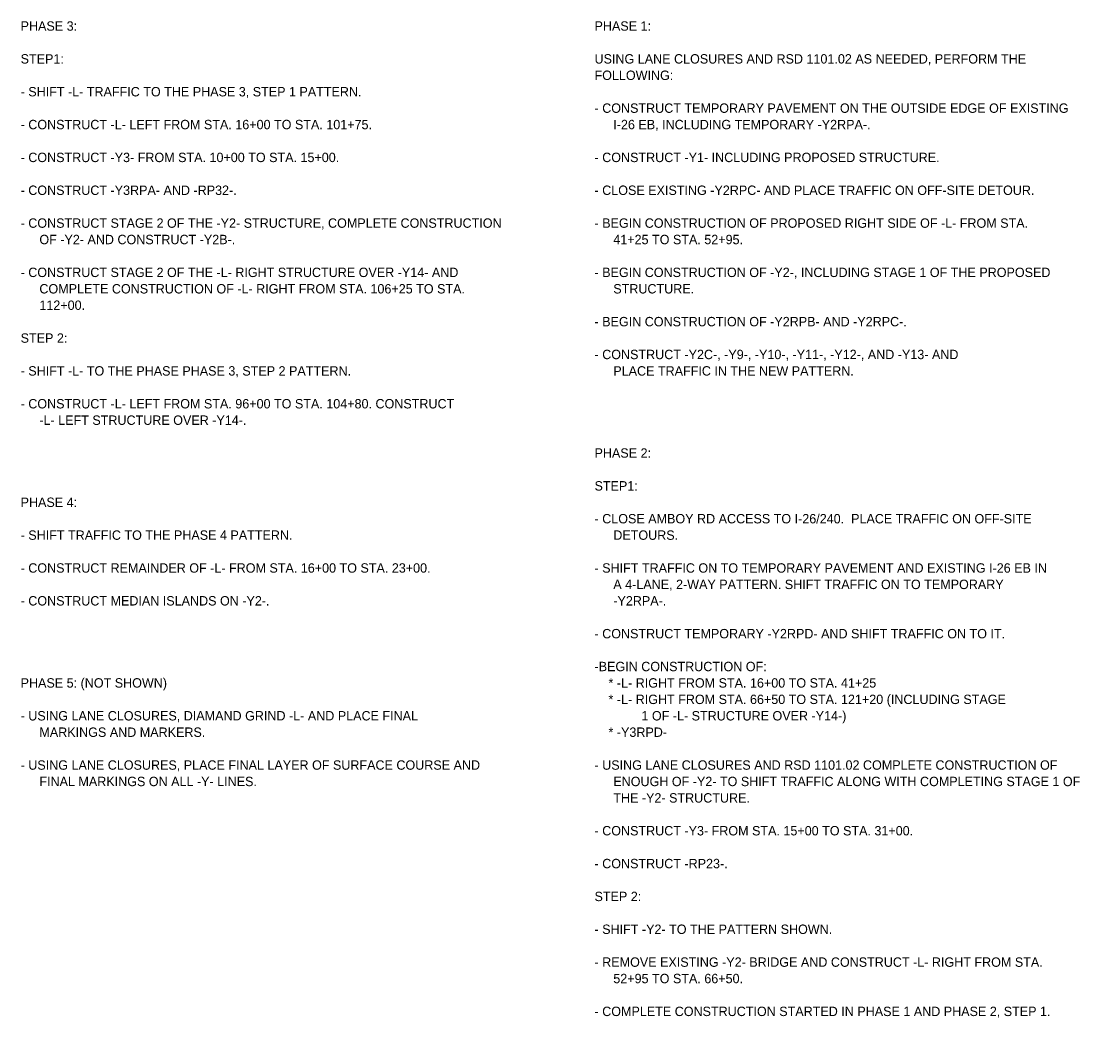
# Model space of a CAD drawing. Extents: x 2483905 to 2494512, y 366160 to 372330.
# Drawn here: x 2485516 to 2486306, y 370427 to 371170 of the extents above; entities that cross this region are included whole.
import ezdxf

# ---------------------------------------------------------------- set-up
doc = ezdxf.new("R2010")
doc.units = 0
doc.layers.add('Scratch_Level_6', color=7, linetype='Continuous')

msp = doc.modelspace()

# ---------------------------------------------------------------- texts
at = {"layer": 'Scratch_Level_6'}
for s, p in [('PHASE 3:', (2485515.8, 371162.6)), ('PHASE 1:', (2485943.99, 371162.6)), ('STEP1:', (2485515.8, 371138.1)), ('USING LANE CLOSURES AND RSD 1101.02 AS NEEDED, PERFORM THE ', (2485943.99, 371138.1)), ('FOLLOWING:', (2485943.99, 371125.86)), ('- SHIFT -L- TRAFFIC TO THE PHASE 3, STEP 1 PATTERN.', (2485515.8, 371113.61)), ('- CONSTRUCT TEMPORARY PAVEMENT ON THE OUTSIDE EDGE OF EXISTING  ', (2485943.99, 371101.36)), ('- CONSTRUCT -L- LEFT FROM STA. 16+00 TO STA. 101+75.', (2485515.8, 371089.12)), ('I-26 EB, INCLUDING TEMPORARY -Y2RPA-.', (2485957.99, 371089.12)), ('- CONSTRUCT -Y3- FROM STA. 10+00 TO STA. 15+00.', (2485515.8, 371064.62)), ('- CONSTRUCT -Y1- INCLUDING PROPOSED STRUCTURE.', (2485943.99, 371064.62)), ('- CONSTRUCT -Y3RPA- AND -RP32-.', (2485515.8, 371040.13)), ('- CLOSE EXISTING -Y2RPC- AND PLACE TRAFFIC ON OFF-SITE DETOUR.', (2485943.99, 371040.13)), ('- CONSTRUCT STAGE 2 OF THE -Y2- STRUCTURE, COMPLETE CONSTRUCTION ', (2485515.8, 371015.64)), ('- BEGIN CONSTRUCTION OF PROPOSED RIGHT SIDE OF -L- FROM STA. ', (2485943.99, 371015.64)), ('OF -Y2- AND CONSTRUCT -Y2B-.', (2485529.8, 371003.39)), ('41+25 TO STA. 52+95.', (2485957.99, 371003.39)), ('- CONSTRUCT STAGE 2 OF THE -L- RIGHT STRUCTURE OVER -Y14- AND ', (2485515.8, 370978.9)), ('- BEGIN CONSTRUCTION OF -Y2-, INCLUDING STAGE 1 OF THE PROPOSED ', (2485943.99, 370978.9)), ('COMPLETE CONSTRUCTION OF -L- RIGHT FROM STA. 106+25 TO STA. ', (2485529.8, 370966.65)), ('STRUCTURE.', (2485957.99, 370966.65)), ('112+00.', (2485529.8, 370954.41)), ('- BEGIN CONSTRUCTION OF -Y2RPB- AND -Y2RPC-.', (2485943.99, 370942.16)), ('STEP 2:', (2485515.8, 370929.91)), ('- CONSTRUCT -Y2C-, -Y9-, -Y10-, -Y11-, -Y12-, AND -Y13- AND ', (2485943.99, 370917.67)), ('- SHIFT -L- TO THE PHASE PHASE 3, STEP 2 PATTERN.', (2485515.8, 370905.42)), ('PLACE TRAFFIC IN THE NEW PATTERN.', (2485957.99, 370905.42)), ('- CONSTRUCT -L- LEFT FROM STA. 96+00 TO STA. 104+80. CONSTRUCT ', (2485515.8, 370880.93)), ('-L- LEFT STRUCTURE OVER -Y14-.', (2485529.8, 370868.68)), ('PHASE 2:', (2485943.99, 370844.19)), ('STEP1:', (2485943.99, 370819.69)), ('PHASE 4:', (2485515.8, 370807.45)), ('- CLOSE AMBOY RD ACCESS TO I-26/240.  PLACE TRAFFIC ON OFF-SITE ', (2485943.99, 370795.2)), ('- SHIFT TRAFFIC TO THE PHASE 4 PATTERN.', (2485515.8, 370782.96)), ('DETOURS.', (2485957.99, 370782.96)), ('- CONSTRUCT REMAINDER OF -L- FROM STA. 16+00 TO STA. 23+00.', (2485515.8, 370758.46)), ('- SHIFT TRAFFIC ON TO TEMPORARY PAVEMENT AND EXISTING I-26 EB IN ', (2485943.99, 370758.46)), ('A 4-LANE, 2-WAY PATTERN. SHIFT TRAFFIC ON TO TEMPORARY          ', (2485957.99, 370746.22)), ('- CONSTRUCT MEDIAN ISLANDS ON -Y2-.', (2485515.8, 370733.97)), ('-Y2RPA-.', (2485957.99, 370733.97)), ('- CONSTRUCT TEMPORARY -Y2RPD- AND SHIFT TRAFFIC ON TO IT.', (2485943.99, 370709.48)), ('-BEGIN CONSTRUCTION OF:', (2485943.99, 370684.98)), ('PHASE 5: (NOT SHOWN)', (2485515.8, 370672.74)), ('    * -L- RIGHT FROM STA. 16+00 TO STA. 41+25', (2485943.99, 370672.74)), ('    * -L- RIGHT FROM STA. 66+50 TO STA. 121+20 (INCLUDING STAGE ', (2485943.99, 370660.49)), ('- USING LANE CLOSURES, DIAMAND GRIND -L- AND PLACE FINAL ', (2485515.8, 370648.24)), ('1 OF -L- STRUCTURE OVER -Y14-)', (2485978.99, 370648.24)), ('MARKINGS AND MARKERS.', (2485529.8, 370636)), ('    * -Y3RPD-', (2485943.99, 370636)), ('- USING LANE CLOSURES, PLACE FINAL LAYER OF SURFACE COURSE AND ', (2485515.8, 370611.5)), ('- USING LANE CLOSURES AND RSD 1101.02 COMPLETE CONSTRUCTION OF ', (2485943.99, 370611.5)), ('FINAL MARKINGS ON ALL -Y- LINES.', (2485529.8, 370599.26)), ('ENOUGH OF -Y2- TO SHIFT TRAFFIC ALONG WITH COMPLETING STAGE 1 OF ', (2485957.99, 370599.26)), ('THE -Y2- STRUCTURE.', (2485957.99, 370587.01)), ('- CONSTRUCT -Y3- FROM STA. 15+00 TO STA. 31+00.', (2485943.99, 370562.52)), ('- CONSTRUCT -RP23-.', (2485943.99, 370538.03)), ('STEP 2:', (2485943.99, 370513.53)), ('- SHIFT -Y2- TO THE PATTERN SHOWN.', (2485943.99, 370489.04)), ('- REMOVE EXISTING -Y2- BRIDGE AND CONSTRUCT -L- RIGHT FROM STA. ', (2485943.99, 370464.55)), ('52+95 TO STA. 66+50.', (2485957.99, 370452.3)), ('- COMPLETE CONSTRUCTION STARTED IN PHASE 1 AND PHASE 2, STEP 1.', (2485943.99, 370427.81))]:
    msp.add_text(s, height=7, rotation=359.99989, dxfattribs=at).set_placement(p)

doc.saveas('drawing.dxf')
